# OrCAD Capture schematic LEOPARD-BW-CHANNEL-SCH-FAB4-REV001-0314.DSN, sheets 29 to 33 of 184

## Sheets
29 150_PVTT_AB_MOSFET: size A3; title: PVTT_AB_MOSFET
30 149_PVDDQ_AB_MOSFET: size C; title: PVDDQ_AB_MOSFET
31 148_PVDDQ_AB_Controller: size C; title: PVDDQ_AB_CONTROLLER
32 147_PVCCIN_CPU1_Decoupling: size A3; title: PVCCIN_CPU1_DECOUPLING
33 146_PVCCIN_CPU1_MOSFET_2: size C; title: PVCCIN_CPU1_MOSFET_2

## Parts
sheet 146_PVCCIN_CPU1_MOSFET_2
PC1456  SCD47U25V3KX-3-GP  [C603H36]
PC1457  SC10U16V5KX-1-GP  [C805H54]
PC1458  SC10U16V5KX-1-GP  [C805H54]
PC1459  SC10U16V5KX-1-GP  [C805H54]
PC1470  SCD1U16V2KX-3GP  [C402H22]
PC1471  SC1U25V3KX-GP  [C603H36]
PC1472  SCD1U16V2KX-3GP  [C402H22]
PC1473  SCD22U16V2KX-GP  [C402H22]
PC1474  SC1U10V2KX-4-GP  [C402H22]
PC1475  SC1U10V2KX-4-GP  [C402H22]
PC1476  SCD47U25V3KX-3-GP  [C603H36]
PC1477  SC10U16V5KX-1-GP  [C805H54]
PC1478  SC10U16V5KX-1-GP  [C805H54]
PC1479  SC10U16V5KX-1-GP  [C805H54]
PC1480  SCD1U16V2KX-3GP  [C402H22]
PC1481  SC1U25V3KX-GP  [C603H36]
PC1482  SCD1U16V2KX-3GP  [C402H22]
PC1483  SC1U10V2KX-4-GP  [C402H22]
PC1484  SCD22U16V2KX-GP  [C402H22]
PC1485  SC1U10V2KX-4-GP  [C402H22]
PG57  COPPER-CLOSE-GP-U  [CON2C-U]
PG58  COPPER-CLOSE-GP-U  [CON2C-U]
PG59  COPPER-CLOSE-GP-U  [CON2C-U]
PG60  COPPER-CLOSE-GP-U  [CON2C-U]
PL83  IND-150NH-15-GP  [L102078-254224H296]
PL84  IND-150NH-15-GP  [L102078-254224H296]
PR32  0R2J-2-GP  [R402H16]
PR33  0R2J-2-GP  [R402H16]
PR50  0R2J-2-GP  [R402H16]
PR51  0R2J-2-GP  [R402H16]
PR2199  1R2F-GP  [R402H16]
PR2202  1R2F-GP  [R402H16]
PR2235  10KR2F-2-GP  [R402H16]
PR2236  10KR2F-2-GP  [R402H16]
PR2257  0R3J-6-GP  [R603H22]
PR2259  0R3J-6-GP  [R603H22]
PR6643  562R2F-GP  [R402H16]
PR6644  562R2F-GP  [R402H16]
PR6645  562R2F-GP  [R402H16]
PR6646  562R2F-GP  [R402H16]
PTP23  TPAD24  [TPAD24]
PTP24  TPAD24  [TPAD24]
PTP25  TPAD24  [TPAD24]
PTP26  TPAD24  [TPAD24]
PU186  TDA21232-GP  [QFN31G5-G4P-7H38]
PU187  TDA21232-GP  [QFN31G5-G4P-7H38]
sheet 147_PVCCIN_CPU1_Decoupling
PC40  SC1U10V2KX-4-GP  [C402H22]
PC41  SC1U10V2KX-4-GP  [C402H22]
PC1285  SC22U6D3V5MX-5-GP  [C805H56]
PC1286  SC22U6D3V5MX-5-GP  [C805H56]
PC1287  SC22U6D3V5MX-5-GP  [C805H56]
PC1288  SC22U6D3V5MX-5-GP  [C805H56]
PC1289  SC22U6D3V5MX-5-GP  [C805H56]
PC1290  SC22U6D3V5MX-5-GP  [C805H56]
PC1291  SC22U6D3V5MX-5-GP  [C805H56]
PC1292  SC22U6D3V5MX-5-GP  [C805H56]
PC1293  SC22U6D3V5MX-5-GP  [C805H56]
PC1294  SC22U6D3V5MX-5-GP  [C805H56]
PC1295  SC22U6D3V5MX-5-GP  [C805H56]
PC1296  SC22U6D3V5MX-5-GP  [C805H56]
PC1297  ST470U2D5VDM-13-GP  [CT7343H83]
PC1298  ST470U2D5VDM-13-GP  [CT7343H83]
PC1299  ST470U2D5VDM-13-GP  [CT7343H83]
PC1300  ST470U2D5VDM-13-GP  [CT7343H83]
PC1301  ST470U2D5VDM-13-GP  [CT7343H83]
PC1302  ST470U2D5VDM-13-GP  [CT7343H83]
PC1303  SC22U6D3V5MX-5-GP  [C805H56]
PC1304  SC22U6D3V5MX-5-GP  [C805H56]
PC1305  SC22U6D3V5MX-5-GP  [C805H56]
PC1306  SC22U6D3V5MX-5-GP  [C805H56]
PC1307  SC22U6D3V5MX-5-GP  [C805H56]
PC1308  SC22U6D3V5MX-5-GP  [C805H56]
PC1309  SC22U6D3V5MX-5-GP  [C805H56]
PC1310  SC22U6D3V5MX-5-GP  [C805H56]
PC1311  SC22U6D3V5MX-5-GP  [C805H56]
PC1312  SC22U6D3V5MX-5-GP  [C805H56]
PC1313  SC22U6D3V5MX-5-GP  [C805H56]
PC1314  SC22U6D3V5MX-5-GP  [C805H56]
PC1315  SC22U6D3V5MX-5-GP  [C805H56]
PC1316  SC22U6D3V5MX-5-GP  [C805H56]
PC1317  SC22U6D3V5MX-5-GP  [C805H56]
PC1318  SC22U6D3V5MX-5-GP  [C805H56]
PC1319  SC22U6D3V5MX-5-GP  [C805H56]
PC1320  SC47U4V5MX-2-GP  [C805H58]
PC1321  SC47U4V5MX-2-GP  [C805H58]
PC1322  SC47U4V5MX-2-GP  [C805H58]
PC1323  SC47U4V5MX-2-GP  [C805H58]
PC1324  SC47U4V5MX-2-GP  [C805H58]
PC1325  SC22U6D3V5MX-5-GP  [C805H56]
PC1326  SC22U6D3V5MX-5-GP  [C805H56]
PC1327  SC22U6D3V5MX-5-GP  [C805H56]
PC1328  SC22U6D3V5MX-5-GP  [C805H56]
PC1329  SC22U6D3V5MX-5-GP  [C805H56]
PC1330  SC22U6D3V5MX-5-GP  [C805H56]
PC1331  SC22U6D3V5MX-5-GP  [C805H56]
PC1332  SC22U6D3V5MX-5-GP  [C805H56]
PC1333  SC22U6D3V5MX-5-GP  [C805H56]
PC1334  SC22U6D3V5MX-5-GP  [C805H56]
PC1335  SC22U6D3V5MX-5-GP  [C805H56]
PC1336  SC22U6D3V5MX-5-GP  [C805H56]
PC1337  SC47U4V5MX-2-GP  [C805H58]
PC1338  SC47U4V5MX-2-GP  [C805H58]
PC1339  SC47U4V5MX-2-GP  [C805H58]
PC1340  SC47U4V5MX-2-GP  [C805H58]
PC1341  SC47U4V5MX-2-GP  [C805H58]
PC1342  SC47U4V5MX-2-GP  [C805H58]
PC1343  SC47U4V5MX-2-GP  [C805H58]
PC1344  SC47U4V5MX-2-GP  [C805H58]
PC1345  SC47U4V5MX-2-GP  [C805H58]
PC1346  SC47U4V5MX-2-GP  [C805H58]
PC1347  SC47U4V5MX-2-GP  [C805H58]
PC1348  SC47U4V5MX-2-GP  [C805H58]
PC1349  SC47U4V5MX-2-GP  [C805H58]
PC1350  SC47U4V5MX-2-GP  [C805H58]
PC1351  SC47U4V5MX-2-GP  [C805H58]
PC1352  SC47U4V5MX-2-GP  [C805H58]
PC1353  SC47U4V5MX-2-GP  [C805H58]
PC1354  SCD1U25V5KX-1GP  [C805H54]
PC1355  SC1U25V6KX-2GP  [C1206H45]
PC1356  SCD1U25V5KX-1GP  [C805H54]
PL66  IND-105NH-GP  [L7065-245152H195]
PR1989  100R2F-L1-GP-U  [R402H14]
PR1990  100R2F-L1-GP-U  [R402H14]
PTC17  E270U16VM-28-GP  [ECAP-100D6D3H363]
PTC18  E270U16VM-28-GP  [ECAP-100D6D3H363]
R6625  100R3F-1-GP  [R603H22]
sheet 148_PVDDQ_AB_Controller
PC1357  SC1KP50V2KX-1GP  [C402H22]
PC1358  SC1U10V2KX-4-GP  [C402H22]
PC1359  SCD1U16V2KX-3GP  [C402H22]
PC1360  SC1U10V2KX-4-GP  [C402H22]
PC1361  SCD1U16V2KX-3GP  [C402H22]
PC1365  SC220P50V2KX-3GP  [C402H22]
PC1366  SCD47U25V3KX-3-GP  [C603H36]
PC1367  SC220P50V2KX-3GP  [C402H22]
PC1368  SC220P50V2JN-3GP  [C402H22]
PC1461  SC220P50V2JN-3GP  [C402H22]
PC1587  SC220P50V2JN-3GP  [C402H22]
PC7331  SCD47U6D3V2KX-1-GP  [C402H22]
PC7332  SCD47U6D3V2KX-1-GP  [C402H22]
PQ9  NST3906F3T5G-GP-U  [SOT-1123CBE1006-1H16]
PR1938  0R2J-2-GP  [R402H16]
PR1991  19K1R2F-GP  [R402H16]
PR1992  1KR2F-3-GP  [R402H16]
PR1993  0R2J-2-GP  [R402H16]
PR1996  1KR2F-3-GP  [R402H16]
PR1999  1KR2F-3-GP  [R402H16]
PR2000  0R2J-2-GP  [R402H16]
PR2001  0R2J-2-GP  [R402H16]
PR2002  10R3F-GP  [R603H22]
PR2004  0R2J-2-GP  [R402H16]
PR2005  0R0402-PAD-1-GP  [0R0402-PAD]
PR2008  16KR2F-GP  [R402H16]
PR2009  8K06R2F-GP  [R402H16]
PR2010  549R2F-GP  [R402H16]
PR2011  16KR2F-GP  [R402H16]
PR2012  10R3F-GP  [R603H22]
PR2013  0R2J-2-GP  [R402H16]
PR2014  0R2J-2-GP  [R402H16]
PR2015  0R2J-2-GP  [R402H16]
PR2016  150R2F-1-GP  [R402H16]
PR2017  0R0402-PAD-1-GP  [0R0402-PAD]
PTP3  TP20B24R10-B-GP  [TP20B24R10-B]
PU13  PX3244HDM-1-GP  [QFN40J5-G3D75H36]
sheet 149_PVDDQ_AB_MOSFET
PC1506  SCD47U25V3KX-3-GP  [C603H36]
PC1507  SC10U16V5KX-1-GP  [C805H54]
PC1508  SC10U16V5KX-1-GP  [C805H54]
PC1509  SC10U16V5KX-1-GP  [C805H54]
PC1510  SCD1U16V2KX-3GP  [C402H22]
PC1511  SC1U25V3KX-GP  [C603H36]
PC1512  SCD1U16V2KX-3GP  [C402H22]
PC1513  SC1U10V2KX-4-GP  [C402H22]
PC1514  SCD22U16V2KX-GP  [C402H22]
PC1515  SC1U10V2KX-4-GP  [C402H22]
PC1516  SCD47U25V3KX-3-GP  [C603H36]
PC1517  SC10U16V5KX-1-GP  [C805H54]
PC1518  SC10U16V5KX-1-GP  [C805H54]
PC1519  SC10U16V5KX-1-GP  [C805H54]
PC1520  SCD1U16V2KX-3GP  [C402H22]
PC1521  SC1U25V3KX-GP  [C603H36]
PC1522  SCD1U16V2KX-3GP  [C402H22]
PC1523  SC1U10V2KX-4-GP  [C402H22]
PC1524  SCD22U16V2KX-GP  [C402H22]
PC1525  SC1U10V2KX-4-GP  [C402H22]
PG61  COPPER-CLOSE-GP-U  [CON2C-U]
PG62  COPPER-CLOSE-GP-U  [CON2C-U]
PG63  COPPER-CLOSE-GP-U  [CON2C-U]
PG65  COPPER-CLOSE-GP-U  [CON2C-U]
PL86  IND-150NH-15-GP  [L102078-254224H296]
PL93  IND-150NH-15-GP  [L102078-254224H296]
PR34  0R2J-2-GP  [R402H16]
PR35  0R2J-2-GP  [R402H16]
PR52  0R2J-2-GP  [R402H16]
PR53  0R2J-2-GP  [R402H16]
PR2208  1R2F-GP  [R402H16]
PR2238  10KR2F-2-GP  [R402H16]
PR2240  1R2F-GP  [R402H16]
PR2241  10KR2F-2-GP  [R402H16]
PR2261  0R3J-6-GP  [R603H22]
PR2263  0R3J-6-GP  [R603H22]
PR6649  562R2F-GP  [R402H16]
PR6650  562R2F-GP  [R402H16]
PR6663  562R2F-GP  [R402H16]
PR6664  562R2F-GP  [R402H16]
PTP29  TPAD24  [TPAD24]
PTP30  TPAD24  [TPAD24]
PTP43  TPAD24  [TPAD24]
PTP44  TPAD24  [TPAD24]
PU189  TDA21232-GP  [QFN31G5-G4P-7H38]
PU196  TDA21232-GP  [QFN31G5-G4P-7H38]
sheet 150_PVTT_AB_MOSFET
PC258  SC1U10V2KX-4-GP  [C402H22]
PC259  SCD22U16V2KX-GP  [C402H22]
PC261  SCD22U16V2KX-GP  [C402H22]
PC263  SC1U25V3KX-GP  [C603H36]
PC266  SC10U16V5KX-1-GP  [C805H54]
PC267  SC10U16V5KX-1-GP  [C805H54]
PC268  SCD47U25V3KX-3-GP  [C603H36]
PC269  SC220P50V2JN-3GP  [C402H22]
PC270  SC47U4V5MX-2-GP  [C805H58]
PC271  SC47U4V5MX-2-GP  [C805H58]
PC272  SC22U6D3V5MX-5-GP  [C805H56]
PC273  SC22U6D3V5MX-5-GP  [C805H56]
PC274  SC22U6D3V5MX-5-GP  [C805H56]
PC275  SC22U6D3V5MX-5-GP  [C805H56]
PC276  SC22U6D3V5MX-5-GP  [C805H56]
PC277  SC22U6D3V5MX-5-GP  [C805H56]
PC278  SC22U6D3V5MX-5-GP  [C805H56]
PC279  SC22U6D3V5MX-5-GP  [C805H56]
PC280  SC22U6D3V5MX-5-GP  [C805H56]
PC281  SC22U6D3V5MX-5-GP  [C805H56]
PC282  SC22U6D3V5MX-5-GP  [C805H56]
PC283  SC22U6D3V5MX-5-GP  [C805H56]
PC284  SE470UF2VDM-GP  [CT7343H83]
PG25  COPPER-CLOSE-GP-U  [CON2C-U]
PG26  COPPER-CLOSE-GP-U  [CON2C-U]
PL15  IND-1UH-101-GP  [L6868-3612H166]
PQ4  NST3906F3T5G-GP-U  [SOT-1123CBE1006-1H16]
PR170  2D2R2F-GP  [R402H16]
PR172  10KR2F-2-GP  [R402H16]
PR173  93K1R2F-L-GP  [R402H16]
PR176  562R2F-GP  [R402H16]
PR177  562R2F-GP  [R402H16]
PR178  0R2F-L-GP  [R402H16]
PR179  0R2F-L-GP  [R402H16]
PR180  120R3F-L-GP  [R603H22]
PR852  0R3J-0-U-GP  [R603H22]
PR853  0R3J-0-U-GP  [R603H22]
PU16  PX3517-GP  [DFN10G3-G2619H36]
PU17  AON7934-GP  [MLP8F3-G2P-1H32]

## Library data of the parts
PC268 PC1366 PC1456 PC1476 PC1506 PC1516 = SCD47U25V3KX-3-GP: CHIP CAP C 0.47U 25V K0603 X7R; GREENDFACTOR: R2_SA;HF_SA;G_SA;; Part Number: 78.47422.2BL; Part Type: SMD-BCG5; SPEC: http://wpqssvr.wistron.com.tw:7001/wpqs/servlet/COM.qpart.Attachment?PartNumber=78.47422.2BL
PC266 PC267 PC1457-PC1459 PC1477-PC1479 PC1507-PC1509 PC1517-PC1519 = SC10U16V5KX-1-GP: CHIP CAP C 10U 16V K0805 X6S; GREENDFACTOR: R2_SA;; Package Type: SMD-BCG5; Part Number: 78.10621.81L; SPEC: http://wpqssvr.wistron.com.tw:7001/wpqs/servlet/COM.qpart.Attachment?PartNumber=78.10621.81L
PC1470 PC1472 PC1480 PC1482 PC1510 PC1512 PC1520 PC1522 = SCD1U16V2KX-3GP: CHIP CAP C 0.1U 16V K0402 X7R; GREENDFACTOR: R2_SA;HF_SA;G_SA;; MAIN_SOURCE: M; Package Type: SMD-BCG; Part Number: 78.10421.2FL; SPEC: http://wpqssvr.wistron.com.tw:7001/wpqs/servlet/COM.qpart.Attachment?PartNumber=78.10421.2FL; Size: 0402; Type: X7R
PC263 PC1471 PC1481 PC1511 PC1521 = SC1U25V3KX-GP: CHIP CAP C 1U 25V K0603 X7R; GREENDFACTOR: R2_SA;HF_SA;G_SA;; Package Type: SMD-BCG; Part Number: 78.10522.2BL; SPEC: http://wpqssvr.wistron.com.tw:7001/wpqs/servlet/COM.qpart.Attachment?PartNumber=78.10522.2BL
PC259 PC261 PC1473 PC1484 PC1514 PC1524 = SCD22U16V2KX-GP: CHIP CAP C 0.22U 16V K0402 X7R; GREENDFACTOR: R2_SA;HF_SA;G_SA;; Package Type: SMD-BCG4; Part Number: 78.22421.2FL; SPEC: http://wpqssvr.wistron.com.tw:7001/wpqs/servlet/COM.qpart.Attachment?PartNumber=78.22421.2FL; Size: 0402; Type: X7R
PC258 PC1358 PC1360 PC1474 PC1475 PC1483 PC1485 PC1513 PC1515 PC1523 PC1525 = SC1U10V2KX-4-GP: CHIP CAP C 1U 10V K 0402 X6S; GREENDFACTOR: R2_SA;HF_SA;; Package Type: SMD-BCG6; Part Number: 78.10523.8FL; SPEC: http://wpqssvr.wistron.com.tw:7001/wpqs/servlet/COM.qpart.Attachment?PartNumber=78.10523.8FL
PG25 PG26 PG57-PG63 PG65 = COPPER-CLOSE-GP-U: COPPER CLOSE; GREENDFACTOR: Regular;; Package Type: DISCRET-G9; Part Number: ZZ.CON2C.XXX; SPEC: http://wpqssvr.wistron.com.tw:7001/wpqs/servlet/COM.qpart.Attachment?PartNumber=ZZ.CON2C.XXX
PL83 PL84 PL86 PL93 = IND-150NH-15-GP: CHIP IND 150NH K FP1007R3-R15-R; GREENDFACTOR: R2_SA;; Part Number: 68.1512N.10E; Part Type: DISCRET-G9; SPEC: http://wpqssvr.wistron.com.tw:7001/wpqs/servlet/COM.qpart.Attachment?PartNumber=68.1512N.10E
PR32-PR35 = 0R2J-2-GP: CHIP RES 0 J 1/16W 0402; GREENDFACTOR: R2_SA;HF_SA;G_SA;; POP?: NOPOP; Package Type: SMD-RG; Part Number: 63.R0034.1DL; SPEC: http://wpqssvr.wistron.com.tw:7001/wpqs/servlet/COM.qpart.Attachment?PartNumber=63.R0034.1DL
PR50-PR53 PR1993 PR2000 PR2001 PR2004 PR2014 PR2015 = 0R2J-2-GP: CHIP RES 0 J 1/16W 0402; GREENDFACTOR: R2_SA;HF_SA;G_SA;; Package Type: SMD-RG; Part Number: 63.R0034.1DL; SPEC: http://wpqssvr.wistron.com.tw:7001/wpqs/servlet/COM.qpart.Attachment?PartNumber=63.R0034.1DL
PR2199 PR2202 PR2208 PR2240 = 1R2F-GP: CHIP RES 1 F 1/16W 0402; GREENDFACTOR: R2_SA;HF_SA;G_SA;; Package Type: SMD-RG; Part Number: 64.1R005.6DL; SPEC: http://wpqssvr.wistron.com.tw:7001/wpqs/servlet/COM.qpart.Attachment?PartNumber=64.1R005.6DL
PR172 PR2235 PR2236 PR2238 PR2241 = 10KR2F-2-GP: CHIP RES 10K F 1/16W 0402; GREENDFACTOR: R2_SA;HF_SA;G_SA;; POP?: NOPOP; Package Type: SMD-RG; Part Number: 64.10025.6DL; SPEC: http://wpqssvr.wistron.com.tw:7001/wpqs/servlet/COM.qpart.Attachment?PartNumber=64.10025.6DL
PR2257 PR2259 PR2261 PR2263 = 0R3J-6-GP: CHIP RES 0 J 1/10W 0603; GREENDFACTOR: R2_SA;HF_SA;G_SA;; Part Number: 63.R0033.15L; Part Type: SMD-RG1; SPEC: http://wpqssvr.wistron.com.tw:7001/wpqs/servlet/COM.qpart.Attachment?PartNumber=63.R0033.15L
PR176 PR177 PR6643-PR6646 PR6649 PR6650 PR6663 PR6664 = 562R2F-GP: CHIP RES 562 F 1/16W 0402; GREENDFACTOR: R2_SA;HF_SA;G_SA;; Package Type: SMD-RG; Part Number: 64.56205.6DL; SPEC: http://wpqssvr.wistron.com.tw:7001/wpqs/servlet/COM.qpart.Attachment?PartNumber=64.56205.6DL
PTP23-PTP26 PTP29 PTP30 PTP43 PTP44 = TPAD24: 24 MILS TEST PAD; GREENDFACTOR: Regular;; Package Type: DISCRET2; Part Number: ZZ.PAD24.001; SPEC: http://wpqssvr.wistron.com.tw:7001/wpqs/servlet/COM.qpart.Attachment?PartNumber=ZZ.PAD24.001
PU186 PU187 PU189 PU196 = TDA21232-GP: IC PWM TDA21232 IQFN 32P; GREENDFACTOR: R2_C;; Part Number: 074.21232.0073; Part Type: DISCRET-GB1; SPEC: http://wpqssvr.wistron.com.tw:7001/wpqs/servlet/COM.qpart.Attachment?PartNumber=074.21232.0073
PC40 PC41 = SC1U10V2KX-4-GP: CHIP CAP C 1U 10V K 0402 X6S; GREENDFACTOR: R2_SA;HF_SA;; Part Number: 78.10523.8FL; Part Type: SMD-BCG6; SPEC: http://wpqssvr.wistron.com.tw:7001/wpqs/servlet/COM.qpart.Attachment?PartNumber=78.10523.8FL
PC1285-PC1296 PC1303-PC1314 PC1325-PC1336 = SC22U6D3V5MX-5-GP: CHIP CAP C 22U 6.3V M0805 X6S; GREENDFACTOR: R2_SA;HF_SA;G_SA;; Package Type: SMD-BCG2; Part Number: 78.22610.81L; SPEC: http://wpqssvr.wistron.com.tw:7001/wpqs/servlet/COM.qpart.Attachment?PartNumber=78.22610.81L; Size: 0805; Type: X6S
PC1297-PC1302 = ST470U2D5VDM-13-GP: CHIP CAP EL 470U 2.5V M7343 ESR4.5 SX; GREENDFACTOR: R2_C;HF_C;; Module: VR_PVCORE_CPU; Package Type: SMD-TCG5; Part Number: 79.4771V.6AL; Part_Spec: 470uF/2.5V/4.5mohm; Quotation: 8_1; SPEC: http://wpqssvr.wistron.com.tw:7001/wpqs/servlet/COM.qpart.Attachment?PartNumber=79.4771V.6AL; VENDOR_PN: EEFSX0E471E4
PC272-PC283 PC1315-PC1319 = SC22U6D3V5MX-5-GP: CHIP CAP C 22U 6.3V M0805 X6S; GREENDFACTOR: R2_SA;HF_SA;G_SA;; Package Type: SMD-BCG2; Part Number: 78.22610.81L; SPEC: http://wpqssvr.wistron.com.tw:7001/wpqs/servlet/COM.qpart.Attachment?PartNumber=78.22610.81L
PC270 PC271 PC1320-PC1324 PC1337-PC1353 = SC47U4V5MX-2-GP: CHIP CAP C 47U 4V M0805 X6S; GREENDFACTOR: R2_SA;HF_SA;G_SA;; Package Type: SMD-BCG3; Part Number: 78.4761T.81L; SPEC: http://wpqssvr.wistron.com.tw:7001/wpqs/servlet/COM.qpart.Attachment?PartNumber=78.4761T.81L
PC1354 PC1356 = SCD1U25V5KX-1GP: CHIP CAP0.1U25V K0805 X7R(ROHS; GREENDFACTOR: R2_SA;HF_SA;G_SA;; Package Type: SMD-BCG; Part Number: 78.10422.21L; SPEC: http://wpqssvr.wistron.com.tw:7001/wpqs/servlet/COM.qpart.Attachment?PartNumber=78.10422.21L
PC1355 = SC1U25V6KX-2GP: CHIP CAP C 1U 25V K1206 X7R; GREENDFACTOR: R2_SA;HF_SA;G_SA;; Package Type: SMD-BCG1; Part Number: 78.10522.22L; SPEC: http://wpqssvr.wistron.com.tw:7001/wpqs/servlet/COM.qpart.Attachment?PartNumber=78.10522.22L
PL66 = IND-105NH-GP: CHIP IND 105NH K FP0705R1-R10-R; GREENDFACTOR: R2_C;; Package Type: DISCRET-G7; Part Number: 68.1052N.101; Part_Spec: 0.105uH/36A/0.25mohm; SPEC: http://wpqssvr.wistron.com.tw:7001/wpqs/servlet/COM.qpart.Attachment?PartNumber=68.1052N.101; Vendor_PN: FP0705R1-R10-R
PR1989 PR1990 = 100R2F-L1-GP-U: CHIP RES 100 F 1/16W 0402; GREENDFACTOR: R2_SA;HF_SA;G_SA;; Package Type: SMD-RG; Part Number: 64.10005.6DL; SPEC: http://wpqssvr.wistron.com.tw:7001/wpqs/servlet/COM.qpart.Attachment?PartNumber=64.10005.6DL
PTC17 PTC18 = E270U16VM-28-GP: CAP EL 270U 16V RT2.5 6.3*8 SOLID CAP; GREENDFACTOR: R2_SA;HF_SA;; Part Number: 09.2771D.E4L; Part Spec: 270uF/16V/10mohm/5A; Part Type: DIP-TCG4; SPEC: http://wpqssvr.wistron.com.tw:7001/wpqs/servlet/COM.qpart.Attachment?PartNumber=09.2771D.E4L
R6625 = 100R3F-1-GP: CHIP RES 100 F 1/10W 0603(ROHS; GREENDFACTOR: R2_SA;HF_SA;G_SA;; Package Type: SMD-RG6; Part Number: 64.10005.55L; SPEC: http://wpqssvr.wistron.com.tw:7001/wpqs/servlet/COM.qpart.Attachment?PartNumber=64.10005.55L
PC1357 = SC1KP50V2KX-1GP: CHIP CAP 1000P50V K0402 X7R(RO; GREENDFACTOR: R2_SA;HF_SA;G_SA;; MAIN_SOURCE: M; Package Type: SMD-BCG; Part Number: 78.10224.2FL; SPEC: http://wpqssvr.wistron.com.tw:7001/wpqs/servlet/COM.qpart.Attachment?PartNumber=78.10224.2FL
PC1359 PC1361 = SCD1U16V2KX-3GP: CHIP CAP C 0.1U 16V K0402 X7R; GREENDFACTOR: R2_SA;HF_SA;G_SA;; MAIN_SOURCE: M; Package Type: SMD-BCG; Part Number: 78.10421.2FL; SPEC: http://wpqssvr.wistron.com.tw:7001/wpqs/servlet/COM.qpart.Attachment?PartNumber=78.10421.2FL
PC1365 PC1367 = SC220P50V2KX-3GP: CHIP CAP 220P50V K0402 X7R(ROH; GREENDFACTOR: R2_SA;HF_SA;G_SA;; MAIN_SOURCE: M; Package Type: SMD-BCG; Part Number: 78.22124.2FL; SPEC: http://wpqssvr.wistron.com.tw:7001/wpqs/servlet/COM.qpart.Attachment?PartNumber=78.22124.2FL
PC269 PC1368 PC1461 PC1587 = SC220P50V2JN-3GP: CHIP CAP C 220P 50V J0402 NPO; GREENDFACTOR: R2_SA;HF_SA;G_SA;; Package Type: SMD-BCG; Part Number: 78.22134.1FL; SPEC: http://wpqssvr.wistron.com.tw:7001/wpqs/servlet/COM.qpart.Attachment?PartNumber=78.22134.1FL
PC7331 PC7332 = SCD47U6D3V2KX-1-GP: CHIP CAP C 0.47U 6.3V K 0402 X6S; GREENDFACTOR: R2_SA;HF_SA;; Package Type: SMD-BCG3; Part Number: 78.47420.8FL; SPEC: http://wpqssvr.wistron.com.tw:7001/wpqs/servlet/COM.qpart.Attachment?PartNumber=78.47420.8FL
PQ4 PQ9 = NST3906F3T5G-GP-U: XTOR NST3906F3T5G PNP SOT-1123; GREENDFACTOR: R2_SA;HF_SA;; Package Type: DISCRET-G5; Part Number: 84.03906.01K; SPEC: http://wpqssvr.wistron.com.tw:7001/wpqs/servlet/COM.qpart.Attachment?PartNumber=84.03906.01K
PR1938 PR2013 = 0R2J-2-GP: CHIP RES 0 J 1/16W 0402; GREENDFACTOR: R2_SA;HF_SA;G_SA;; Part Number: 63.R0034.1DL; Part Type: SMD-RG; SPEC: http://wpqssvr.wistron.com.tw:7001/wpqs/servlet/COM.qpart.Attachment?PartNumber=63.R0034.1DL
PR1991 = 19K1R2F-GP: CHIP RES 19.1K F 1/16W 0402; GREENDFACTOR: R2_SA;HF_SA;G_SA;; Part Number: 64.19125.6DL; Part Type: RCL_GP; SPEC: http://wpqssvr.wistron.com.tw:7001/wpqs/servlet/COM.qpart.Attachment?PartNumber=64.19125.6DL
PR1992 PR1996 PR1999 = 1KR2F-3-GP: CHIP RES 1K F 1/16W 0402; GREENDFACTOR: R2_SA;HF_SA;G_SA;; Package Type: SMD-RG; Part Number: 64.10015.6DL; SPEC: http://wpqssvr.wistron.com.tw:7001/wpqs/servlet/COM.qpart.Attachment?PartNumber=64.10015.6DL
PR2002 PR2012 = 10R3F-GP: CHIP RES 10 F 1/10W 0603; GREENDFACTOR: R2_SA;HF_SA;G_SA;; Level: SMD; Package Type: RCL_GP; Part Number: 64.10R05.55L; Part Type: RCL_GP; SPEC: http://wpqssvr.wistron.com.tw:7001/wpqs/servlet/COM.qpart.Attachment?PartNumber=64.10R05.55L; Status: POP
PR2005 PR2017 = 0R0402-PAD-1-GP: DUMMY PAD WITH WIRE RES 0 0402; GREENDFACTOR: R_C;; Module: VR_CPU_PVCC; Package Type: SMD-RG2; Part Number: ZZ.R0402.001; Part Type: SMD-RG2; Quotation: 8_1; SPEC: http://wpqssvr.wistron.com.tw:7001/wpqs/servlet/COM.qpart.Attachment?PartNumber=ZZ.R0402.001
PR2008 = 16KR2F-GP: CHIP RES 16K F 1/16W 0402; GREENDFACTOR: R2_SA;HF_SA;G_SA;; Module: VR_PVCORE_CPU; POP?: NOPOP; Package Type: SMD-RG; Part Number: 64.16025.6DL; Quotation: 8_1; SPEC: http://wpqssvr.wistron.com.tw:7001/wpqs/servlet/COM.qpart.Attachment?PartNumber=64.16025.6DL
PR2009 = 8K06R2F-GP: CHIP RES 8.06K F 1/16W 0402; GREENDFACTOR: R2_SA;HF_SA;G_SA;; Package Type: RCL_GP; Part Number: 64.80615.6DL; SPEC: http://wpqssvr.wistron.com.tw:7001/wpqs/servlet/COM.qpart.Attachment?PartNumber=64.80615.6DL
PR2010 = 549R2F-GP: CHIP RES 549 F 1/16W 0402; GREENDFACTOR: R2_SA;HF_SA;; Package Type: RCL_GP; Part Number: 64.54905.6DL; SPEC: http://wpqssvr.wistron.com.tw:7001/wpqs/servlet/COM.qpart.Attachment?PartNumber=64.54905.6DL
PR2011 = 16KR2F-GP: CHIP RES 16K F 1/16W 0402; GREENDFACTOR: R2_SA;HF_SA;G_SA;; Module: VR_PVCORE_CPU; Package Type: SMD-RG; Part Number: 64.16025.6DL; Quotation: 8_1; SPEC: http://wpqssvr.wistron.com.tw:7001/wpqs/servlet/COM.qpart.Attachment?PartNumber=64.16025.6DL
PR2016 = 150R2F-1-GP: CHIP RES 150 F 1/16W 0402; GREENDFACTOR: R2_SA;HF_SA;G_SA;; Package Type: SMD-RG; Part Number: 64.15005.6DL; SPEC: http://wpqssvr.wistron.com.tw:7001/wpqs/servlet/COM.qpart.Attachment?PartNumber=64.15005.6DL
PTP3 = TP20B24R10-B-GP_4: TEST VIA FOR DRILL 10MIL; GREENDFACTOR: R2_C;; Package Type: DISCRET-G5; Part Number: ZZ.0TPAD.211; SPEC: http://wpqssvr.wistron.com.tw:7001/wpqs/servlet/COM.qpart.Attachment?PartNumber=ZZ.0TPAD.211
PU13 = PX3244HDM-1-GP: IC CONVERTER PX3244HDM QFN 40P; GREENDFACTOR: R2_SA;; Part Number: 074.03244.0043; Part Type: ASIC-G5; SPEC: http://wpqssvr.wistron.com.tw:7001/wpqs/servlet/COM.qpart.Attachment?PartNumber=074.03244.0043
PC284 = SE470UF2VDM-GP: CHIP CAP 470UF 2V EEFSX0D471X; GREENDFACTOR: R_SA;; Module: VR_DDR_P1V5_VDDQ; Package Type: SMD-TCG1; Part Number: 79.47719.2BL; Part Type: SMD-TCG1; Part_Function: Cout_bulk; Part_Spec: 470uF/2V/6mohm; Part_Type: Solid_al_cap; SPEC: http://wpqssvr.wistron.com.tw:7001/wpqs/servlet/COM.qpart.Attachment?PartNumber=79.47719.2BL; VENDOR_PN: EEFSX0D471XE
PL15 = IND-1UH-101-GP: CHIP IND 1UH HCP0704-1R0-R; GREENDFACTOR: R2_SA;; Package Type: DISCRET-G6; Part Number: 68.1R090.10B; Part_Spec: 1.0uH/6.2mohm/17A; SPEC: http://wpqssvr.wistron.com.tw:7001/wpqs/servlet/COM.qpart.Attachment?PartNumber=68.1R090.10B; Vendor_PN: HCP0704-1R0-R
PR170 = 2D2R2F-GP: CHIP RES 2.2 F 1/16W 0402; GREENDFACTOR: R2_SA;HF_SA;G_SA;; Package Type: SMD-RG1; Part Number: 64.2R205.6DL; SPEC: http://wpqssvr.wistron.com.tw:7001/wpqs/servlet/COM.qpart.Attachment?PartNumber=64.2R205.6DL
PR173 = 93K1R2F-L-GP: CHIP RES 93.1K F 1/16W 0402; GREENDFACTOR: R2_SA;HF_SA;G_SA;; Package Type: SMD-RG; Part Number: 64.93125.6DL; SPEC: http://wpqssvr.wistron.com.tw:7001/wpqs/servlet/COM.qpart.Attachment?PartNumber=64.93125.6DL
PR178 PR179 = 0R2F-L-GP: CHIP RES 0 F 0402 RK73Z1ETTP KOA; GREENDFACTOR: R2_SA;; Package Type: SMD-RG5; Part Number: 64.R0005.L0L; SPEC: http://wpqssvr.wistron.com.tw:7001/wpqs/servlet/COM.qpart.Attachment?PartNumber=64.R0005.L0L
PR180 = 120R3F-L-GP: CHIP RES 120 F 1/10W 0603; GREENDFACTOR: R2_SA;HF_SA;G_SA;; Package Type: SMD-RG; Part Number: 64.12005.55L; SPEC: http://wpqssvr.wistron.com.tw:7001/wpqs/servlet/COM.qpart.Attachment?PartNumber=64.12005.55L
PR852 PR853 = 0R3J-0-U-GP: CHIP RES 0 J 1/10W 0603; GREENDFACTOR: R2_SA;HF_SA;G_SA;; Package Type: RCL_GP; Part Number: 63.00000.00L; SPEC: http://wpqssvr.wistron.com.tw:7001/wpqs/servlet/COM.qpart.Attachment?PartNumber=63.00000.00L
PU16 = PX3517-GP: IC MOS DRV PX3517 DFN 10P; GREENDFACTOR: R2_C;; Module: VR_PVCORE_CPU; Package Type: DISCRET-G9; Part Number: 74.03517.0E3; Quotation: 8_1; SPEC: http://wpqssvr.wistron.com.tw:7001/wpqs/servlet/COM.qpart.Attachment?PartNumber=74.03517.0E3
PU17 = AON7934-GP: FET MOS AON7934 NC POWER DFN3X3A; GREENDFACTOR: R2_SA;HF_SA;; Part Number: 84.07934.037; Part Type: DISCRET-G7; SPEC: http://wpqssvr.wistron.com.tw:7001/wpqs/servlet/COM.qpart.Attachment?PartNumber=84.07934.037

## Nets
GND: PC40.2 PC41.2 PC258.2 PC259.2 PC261.2 PC263.2 PC266.2 PC267.2 PC269.1 PC270.2 PC271.2 PC272.2 PC273.2 PC274.2 PC275.2 PC276.2 PC277.2 PC278.2 PC279.2 PC280.2 PC281.2 PC282.2 PC283.2 PC284.2 PC1285.2 PC1286.2 PC1287.2 PC1288.2 PC1289.2 PC1290.2 PC1291.2 PC1292.2 PC1293.2 PC1294.2 PC1295.2 PC1296.2 PC1297.2 PC1298.2 PC1299.2 PC1300.2 PC1301.2 PC1302.2 PC1303.2 PC1304.2 PC1305.2 PC1306.2 PC1307.2 PC1308.2 PC1309.2 PC1310.2 PC1311.2 PC1312.2 PC1313.2 PC1314.2 PC1315.2 PC1316.2 PC1317.2 PC1318.2 PC1319.2 PC1320.2 PC1321.2 PC1322.2 PC1323.2 PC1324.2 PC1325.2 PC1326.2 PC1327.2 PC1328.2 PC1329.2 PC1330.2 PC1331.2 PC1332.2 PC1333.2 PC1334.2 PC1335.2 PC1336.2 PC1337.2 PC1338.2 PC1339.2 PC1340.2 PC1341.2 PC1342.2 PC1343.2 PC1344.2 PC1345.2 PC1346.2 PC1347.2 PC1348.2 PC1349.2 PC1350.2 PC1351.2 PC1352.2 PC1353.2 PC1354.2 PC1355.2 PC1356.2 PC1357.2 PC1358.2 PC1359.2 PC1360.2 PC1361.2 PC1368.1 PC1457.2 PC1458.2 PC1459.2 PC1461.1 PC1470.2 PC1471.2 PC1472.2 PC1473.1 PC1474.1 PC1475.1 PC1477.2 PC1478.2 PC1479.2 PC1480.2 PC1481.2 PC1482.2 PC1483.1 PC1484.1 PC1485.1 PC1507.2 PC1508.2 PC1509.2 PC1510.2 PC1511.2 PC1512.2 PC1513.1 PC1514.1 PC1515.1 PC1517.2 PC1518.2 PC1519.2 PC1520.2 PC1521.2 PC1522.2 PC1523.1 PC1524.1 PC1525.1 PC1587.1 PQ4.B PQ4.C PQ9.B PQ9.C PR32.2 PR33.2 PR34.2 PR35.2 PR173.1 PR179.1 PR180.2 PR1990.1 PR1992.2 PR2008.1 PR2009.1 PR2011.1 PTC17.2 PTC18.2 PU13.1(BVR_READY) PU13.22(ISEN3N) PU13.37(DNC#37) PU13.41(GND) PU16.5(GND) PU16.11(GND) PU17.5(S2#5) PU17.6(S2#6) PU17.7(S2#7) PU186.4(AGND) PU186.12(PGND) PU186.13(PGND) PU186.14(PGND) PU186.15(PGND) PU186.28(PGND) PU186.32(PGND) PU186.34(PGND) PU187.4(AGND) PU187.12(PGND) PU187.13(PGND) PU187.14(PGND) PU187.15(PGND) PU187.28(PGND) PU187.32(PGND) PU187.34(PGND) PU189.4(AGND) PU189.12(PGND) PU189.13(PGND) PU189.14(PGND) PU189.15(PGND) PU189.28(PGND) PU189.32(PGND) PU189.34(PGND) PU196.4(AGND) PU196.12(PGND) PU196.13(PGND) PU196.14(PGND) PU196.15(PGND) PU196.28(PGND) PU196.32(PGND) PU196.34(PGND) R6625.2 ; also on sheet 1 2 3 4 5 6 7 8 9 10 11 12 13 14 15 16 17 18 19 20 21 22 23 24 25 26 27 28 34 35 36 37 38 39 44 46 47 49 50 51 52 53 54 55 56 57 58 59 60 61 62 63 64 65 66 69 70 71 73 74 75 76 78 79 80 81 82 83 84 86 87 88 89 90 91 92 93 94 95 96 97 98 99 100 101 102 103 104 105 106 107 108 109 110 111 112 113 114 115 116 117 118 119 128 129 138 139 159 160 161 166 168 169 170 171 172 173 174 175 176 177 180 181 182 183 184
P3V3_STBY: PR50.2 PR51.2 PR52.2 PR53.2 PR1993.1 PR1996.1 PR1999.1 ; also on sheet 2 3 5 6 8 9 10 11 12 15 16 17 20 21 22 25 26 27 34 35 37 38 39 45 47 49 50 51 52 54 55 59 60 61 62 63 64 65 66 69 70 71 72 73 74 76 79 83 84 87 88 89 90 91 92 93 94 95 96 97 98 99 159 161 166 168 173 174 176 177 179 180 182 183 184
P5V_STBY: PC1473.2 PC1475.2 PC1484.2 PC1485.2 PC1514.2 PC1515.2 PC1524.2 PC1525.2 PR170.1 PR2199.1 PR2202.1 PR2208.1 PR2240.1 PU186.29(PVCC) PU187.29(PVCC) PU189.29(PVCC) PU196.29(PVCC) ; also on sheet 4 5 6 8 14 15 19 20 24 25 34 37 38 59 61 65 69 76 95
P12V_STBY: PC1354.1 PC1355.1 PL66.1 ; also on sheet 2 3 4 7 9 10 11 12 13 17 18 22 23 27 28 36 59 60 75 95 104 105 106 107 108 109 110 111 112 113 114 115 116 117 118 119
PVCCIN_CPU1: PC40.1 PC41.1 PC1285.1 PC1286.1 PC1287.1 PC1288.1 PC1289.1 PC1290.1 PC1291.1 PC1292.1 PC1293.1 PC1294.1 PC1295.1 PC1296.1 PC1297.1 PC1298.1 PC1299.1 PC1300.1 PC1301.1 PC1302.1 PC1303.1 PC1304.1 PC1305.1 PC1306.1 PC1307.1 PC1308.1 PC1309.1 PC1310.1 PC1311.1 PC1312.1 PC1313.1 PC1314.1 PC1315.1 PC1316.1 PC1317.1 PC1318.1 PC1319.1 PC1320.1 PC1321.1 PC1322.1 PC1323.1 PC1324.1 PC1325.1 PC1326.1 PC1327.1 PC1328.1 PC1329.1 PC1330.1 PC1331.1 PC1332.1 PC1333.1 PC1334.1 PC1335.1 PC1336.1 PC1337.1 PC1338.1 PC1339.1 PC1340.1 PC1341.1 PC1342.1 PC1343.1 PC1344.1 PC1345.1 PC1346.1 PC1347.1 PC1348.1 PC1349.1 PC1350.1 PC1351.1 PC1352.1 PC1353.1 PG58.2 PG60.2 PL83.2(F) PL84.2(F) PR1989.1 R6625.1 ; also on sheet 34 120
PVCCIN_CPU1_BOOT4: PR2257.1 PU187.5(BOOT)
PVCCIN_CPU1_BOOT5: PR2259.1 PU186.5(BOOT)
PVCCIN_CPU1_EN4: PR50.1 PU187.31(EN)
PVCCIN_CPU1_EN5: PR51.1 PU186.31(EN)
PVCCIN_CPU1_GH4: PTP26.1 PU187.6(GH)
PVCCIN_CPU1_GH5: PTP24.1 PU186.6(GH)
PVCCIN_CPU1_GL4: PTP25.1 PU187.27(GL#27)
PVCCIN_CPU1_GL5: PTP23.1 PU186.27(GL#27)
PVCCIN_CPU1_ISEN4N: PR6646.2 ; also on sheet 35
PVCCIN_CPU1_ISEN4P: PG58.1 ; also on sheet 35
PVCCIN_CPU1_ISEN5N: PR6643.2 ; also on sheet 35
PVCCIN_CPU1_ISEN5P: PG60.1 ; also on sheet 35
PVCCIN_CPU1_PHASE4: PC1476.2 PU187.7(PHASE)
PVCCIN_CPU1_PHASE4_R: PC1476.1 PR2257.2
PVCCIN_CPU1_PHASE5: PC1456.2 PU186.7(PHASE)
PVCCIN_CPU1_PHASE5_R: PC1456.1 PR2259.2
PVCCIN_CPU1_PWM4: PU187.1(PWM) ; also on sheet 35
PVCCIN_CPU1_PWM5: PU186.1(PWM) ; also on sheet 35
PVCCIN_CPU1_SW#4: PG57.2 PL84.1(S) PU187.16(SW#16) PU187.17(SW#17) PU187.18(SW#18) PU187.19(SW#19) PU187.20(SW#20) PU187.21(SW#21) PU187.22(SW#22) PU187.23(SW#23) PU187.24(NC#24) PU187.25(NC#25) PU187.26(NC#26)
PVCCIN_CPU1_SW#4_N: PG57.1 PR6645.2
PVCCIN_CPU1_SW#4_R: PR6645.1 PR6646.1
PVCCIN_CPU1_SW#5: PG59.2 PL83.1(S) PU186.16(SW#16) PU186.17(SW#17) PU186.18(SW#18) PU186.19(SW#19) PU186.20(SW#20) PU186.21(SW#21) PU186.22(SW#22) PU186.23(SW#23) PU186.24(NC#24) PU186.25(NC#25) PU186.26(NC#26)
PVCCIN_CPU1_SW#5_N: PG59.1 PR6644.2
PVCCIN_CPU1_SW#5_R: PR6643.1 PR6644.1
PVCCIN_CPU1_TMON4: PR32.1 PU187.30(PHFLT#)
PVCCIN_CPU1_TMON5: PR33.1 PU186.30(PHFLT#)
PVCCIN_CPU1_VCC4: PC1483.2 PR2202.2 PR2236.2 PU187.3(VCC)
PVCCIN_CPU1_VCC5: PC1474.2 PR2199.2 PR2235.2 PU186.3(VCC)
PVCCIN_CPU1_VIN: PC1356.1 PC1457.1 PC1458.1 PC1459.1 PC1470.1 PC1471.1 PC1472.1 PC1477.1 PC1478.1 PC1479.1 PC1480.1 PC1481.1 PC1482.1 PL66.2 PTC17.1 PTC18.1 PU186.8(VIN) PU186.9(VIN) PU186.10(VIN) PU186.11(VIN) PU186.33(VIN) PU187.8(VIN) PU187.9(VIN) PU187.10(VIN) PU187.11(VIN) PU187.33(VIN) ; also on sheet 34 35
PVCCIN_CPU1_ZCD#4: PR2236.1 PU187.2(NC#2)
PVCCIN_CPU1_ZCD#5: PR2235.1 PU186.2(NC#2)
PVDDQ_AB: PG62.2 PG65.2 PL86.2(F) PL93.2(F) ; also on sheet 28 45 52 97 116 117 118 119 130 139
PVDDQ_AB_ALERT: PR2014.2 PU13.13(ALERT#)
PVDDQ_AB_BOOT1: PR2261.1 PU189.5(BOOT)
PVDDQ_AB_BOOT2: PR2263.1 PU196.5(BOOT)
PVDDQ_AB_EN: PR2000.2 PU13.8(VR_EN)
PVDDQ_AB_EN1: PR52.1 PU189.31(EN)
PVDDQ_AB_EN2: PR53.1 PU196.31(EN)
PVDDQ_AB_FAULT: PR2004.1 PU13.38(FAULT1)
PVDDQ_AB_GH1: PTP30.1 PU189.6(GH)
PVDDQ_AB_GH2: PTP44.1 PU196.6(GH)
PVDDQ_AB_GL1: PTP29.1 PU189.27(GL#27)
PVDDQ_AB_GL2: PTP43.1 PU196.27(GL#27)
PVDDQ_AB_IMON: PTP3.1 PU13.20(IMON/FAULT2)
PVDDQ_AB_ISEN1N: PC7331.2 PR6650.2 PU13.28(ISEN1N)
PVDDQ_AB_ISEN1P: PC7331.1 PG62.1 PU13.29(ISEN1P)
PVDDQ_AB_ISEN2N: PC7332.2 PR6664.2 PU13.25(ISEN2N)
PVDDQ_AB_ISEN2P: PC7332.1 PG65.1 PU13.26(ISEN2P)
PVDDQ_AB_PG: PR1996.2 PR2001.2 PU13.7(VR_READY)
PVDDQ_AB_PHASE1: PC1506.2 PU189.7(PHASE)
PVDDQ_AB_PHASE1_R: PC1506.1 PR2261.2
PVDDQ_AB_PHASE2: PC1516.2 PU196.7(PHASE)
PVDDQ_AB_PHASE2_R: PC1516.1 PR2263.2
PVDDQ_AB_PWM1: PU13.4(PWM1) PU189.1(PWM)
PVDDQ_AB_PWM2: PU13.5(PWM2) PU196.1(PWM)
PVDDQ_AB_SADDR_L: PR2009.2 PU13.24(SADDR_L)
PVDDQ_AB_SADDR_M: PR2008.2 PU13.21(SADDR_M)
PVDDQ_AB_SW#1: PG61.2 PL86.1(S) PU189.16(SW#16) PU189.17(SW#17) PU189.18(SW#18) PU189.19(SW#19) PU189.20(SW#20) PU189.21(SW#21) PU189.22(SW#22) PU189.23(SW#23) PU189.24(NC#24) PU189.25(NC#25) PU189.26(NC#26)
PVDDQ_AB_SW#1_N: PG61.1 PR6649.2
PVDDQ_AB_SW#1_R: PR6649.1 PR6650.1
PVDDQ_AB_SW#2: PG63.2 PL93.1(S) PU196.16(SW#16) PU196.17(SW#17) PU196.18(SW#18) PU196.19(SW#19) PU196.20(SW#20) PU196.21(SW#21) PU196.22(SW#22) PU196.23(SW#23) PU196.24(NC#24) PU196.25(NC#25) PU196.26(NC#26)
PVDDQ_AB_SW#2_N: PG63.1 PR6663.2
PVDDQ_AB_SW#2_R: PR6663.1 PR6664.1
PVDDQ_AB_TMON1: PR34.1 PU189.30(PHFLT#)
PVDDQ_AB_TMON2: PR35.1 PU196.30(PHFLT#)
PVDDQ_AB_TSEN: PC1587.2 PR1938.1 PU13.27(TSEN)
PVDDQ_AB_TSEN_R: PC1461.2 PQ9.E PR1938.2
PVDDQ_AB_VADDR: PR2011.2 PU13.17(VADDR)
PVDDQ_AB_VCC1: PC1513.2 PR2208.2 PR2238.2 PU189.3(VCC)
PVDDQ_AB_VCC2: PC1523.2 PR2240.2 PR2241.2 PU196.3(VCC)
PVDDQ_AB_VCLK: PR2016.2 PU13.11(VCLK)
PVDDQ_AB_VD15: PC1360.1 PC1361.1 PU13.40(VD15)
PVDDQ_AB_VDD: PC1358.1 PC1359.1 PR1993.2 PU13.31(VDD)
PVDDQ_AB_VDIO: PR2015.2 PU13.12(VDIO)
PVDDQ_AB_VIN: PC261.1 PC263.1 PC266.1 PC267.1 PC1507.1 PC1508.1 PC1509.1 PC1510.1 PC1511.1 PC1512.1 PC1517.1 PC1518.1 PC1519.1 PC1520.1 PC1521.1 PC1522.1 PR1991.2 PU17.2(D1#2) PU17.3(D1#3) PU17.4(D1#4) PU17.9(D1#9) PU189.8(VIN) PU189.9(VIN) PU189.10(VIN) PU189.11(VIN) PU189.33(VIN) PU196.8(VIN) PU196.9(VIN) PU196.10(VIN) PU196.11(VIN) PU196.33(VIN) ; also on sheet 28
PVDDQ_AB_VINSEN: PC1357.1 PR1991.1 PR1992.1 PU13.30(VINSEN)
PVDDQ_AB_VSENN: PC1365.2 PR2005.2 PU13.19(VSENN)
PVDDQ_AB_VSENN_R: PR2005.1 ; also on sheet 28
PVDDQ_AB_VSENP: PC1365.1 PR2002.1 PU13.18(VSENP)
PVDDQ_AB_VSENP_R: PR2002.2 ; also on sheet 28
PVDDQ_AB_ZCD#1: PR2238.1 PU189.2(NC#2)
PVDDQ_AB_ZCD#2: PR2241.1 PU196.2(NC#2)
IRQ_PVDDQ_AB_VRHOT_LVT3_N: PR1999.2 PU13.39(VR_HOT#) ; also on sheet 177 181
PVPP_AB_PWRGD: PR2000.1 ; also on sheet 27
PVTT_AB: PC270.1 PC271.1 PC272.1 PC273.1 PC274.1 PC275.1 PC276.1 PC277.1 PC278.1 PC279.1 PC280.1 PC281.1 PC282.1 PC283.1 PC284.1 PG26.2 PL15.2(S) PR178.1 PR180.1 ; also on sheet 116 117 118 119
PVTT_AB_BISEN_N: PR176.2 PR177.1
PVTT_AB_BISEN_N_R: PG25.1 PR176.1
PVTT_AB_BISENN: PC1366.2 PR177.2 PR2010.2 PU13.33(BISENN)
PVTT_AB_BISENP: PC1366.1 PG26.1 PR2010.1 PU13.34(BISENP)
PVTT_AB_BPWM: PU13.2(BPWM) PU16.4(PWM)
PVTT_AB_BST: PC268.1 PU16.2(BOOT)
PVTT_AB_BTSEN: PC1368.2 PR2013.2 PU13.32(BTSEN)
PVTT_AB_BTSEN_R: PC269.2 PQ4.E PR2013.1
PVTT_AB_BVSENN: PC1367.2 PR2017.2 PU13.35(BVSENN)
PVTT_AB_BVSENP: PC1367.1 PR2012.1 PU13.36(BVSENP)
PVTT_AB_LGATE: PR852.2 PU16.6(LGATE)
PVTT_AB_LGATE_R: PR852.1 PU17.8(G2)
PVTT_AB_PH: PC268.2 PG25.2 PL15.1(F) PR172.2 PU16.10(PHASE) PU17.10(S1/D2)
PVTT_AB_PVCC: PC258.1 PC259.1 PR170.2 PU16.7(VCC) PU16.9(PVCC)
PVTT_AB_RT: PR173.2 PU16.8(RT)
PVTT_AB_UGATE: PR172.1 PR853.2 PU16.1(UGATE)
PVTT_AB_UGATE_R: PR853.1 PU17.1(G1)
PVTT_AB_VSENN_R: PR179.2 PR2017.1
PVTT_AB_VSENP_R: PR178.2 PR2012.2
PWRGD_PVPP_PVDDQ_AB: PR2001.1 ; also on sheet 51
SMB_VR_STBY_LVC3_CLK: PU13.10(SCL) ; also on sheet 16 21 26 35 39 74 161
SMB_VR_STBY_LVC3_DATA: PU13.9(SDA) ; also on sheet 16 21 26 35 39 74 161
SVID_ALERT_CPU0_N: PR2014.1 ; also on sheet 26 39 139
SVID_CLK_CPU0: PR2016.1 ; also on sheet 26 39 139
SVID_DIO_CPU0: PR2015.1 ; also on sheet 26 39 139
VR_FAIL_PVCC_CPU_N: PR2004.2 ; also on sheet 16 21 26 35 39 74
VSENSE_PVCCIN_CPU1_N: PR1990.2 ; also on sheet 35 120
VSENSE_PVCCIN_CPU1_P: PR1989.2 ; also on sheet 35 120

Not connected (* = marked no-connect by the designer): PU13 3(DR_EN)* 6(PWM3)* 14(RESET#)* 15(DNC#15)* 16(DNC#16)* 23(ISEN3P)*; PU16 3(THW#)*; PU186 35(GL#35)*; PU187 35(GL#35)*; PU189 35(GL#35)*; PU196 35(GL#35)*

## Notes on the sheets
sheet 29
- Power rail : PVTT_AB
  Controller : PX3244H+PX3517+BSZ0907
  TDC : 2A
  Max : 3.6A
  OCP : 6A
  Sinking/Souring : +/-1.14A
  Max Transient Sinking : -1.02A
  Max Transient Sourcing : +0.46A
  Slew rate : 4.67A
  Step Size : 1.48A
- FAB1 REV013 20150413
- Change to 63.00000.00L
- FAB1 REV008 20150326
- Differential Pair
- Place near PL15
- Differential Pair
- Place at the middle of the central DIM
- Routed As Differential Pair
- Place After Lout
- Memory Slot Capacitors
- Place Capcitors Under Output Inductors on Bottom Side
sheet 30
- PVDDQ_AB_MOSFET
- FP1007R3-R15-R
  150nH/0.29mohm/61A
  7.8*10.2*7.3 mm
- FP1007R3-R15-R
  150nH/0.29mohm/61A
  7.8*10.2*7.3 mm
sheet 31
- Power rail : PVDDQ_AB
  Controller : PX3244H
  Min current : 2.59A
  TDC : 36.93A
  Max : 37.87A
  Step Size : 35.28A
  Slew rate : 16.72 A/us
  OCP : 46A
  I2C address : 08
  SVID address : 02
  DDR Type : LR-DIMM
  Level : DDR4
  Process (nm Technology) : 2x
  Physical Rank : 4
  DRAM width : x4
  Speed (MHz) : 2400
  DRAM tech : 4Gb
  DPC (DIMM Per Channel) : 2
  Page : open
  Burst Length : 8
  # of CH/Skt used :4
  Refresh : 2x
  # Memory CHs/VR for VDD/VTT : 2
  # Memory CHs/VR for VPP : 2
- Routed As Differential Pair
- close Phase 1 between phase 2
- Routed As Differential Pair
- Routed As Differential Pair
- VDDQ Measurement point for Bode
- Routed As Differential Pair
- PVDDQ_AB I2C address:08
- Routed As Differential Pair
- PVDDQ_AB SVID address:02
- Use Daisy Chain
- PDG P.252
- Vtt Measurement point for Bode
- Routed As Differential Pair
- Routed As Differential Pair
sheet 32
- PVCCIN CPU1 Decoupling
- Place in CPU Socket Cavity
- Place Capacitors Under Output Inductors on Bottom Side
- 25x22uF place on BOTTOM side PCB inside CPU socket cavity
- Place After Lout
- Place Capcitors Around Outside CPU Socket
- 17x47uF place on TOP side PCB inside CPU socket cavity
- CPU1 LC Filter
- 4x22uF place on TOP side PCB inside CPU socket cavity
- 2x1uF place on Bottom side PCB
   inside CPU socket cavity
- To Remote Sense
- Routed As Differential Pair
- To Local Sense
sheet 33
- PVCCIN_CPU1_MOSFET_2
- FP1007R3-R15-R
  150nH/0.29mohm/61A
  7.8*10.2*7.3 mm
- FP1007R3-R15-R
  150nH/0.29mohm/61A
  7.8*10.2*7.3 mm
